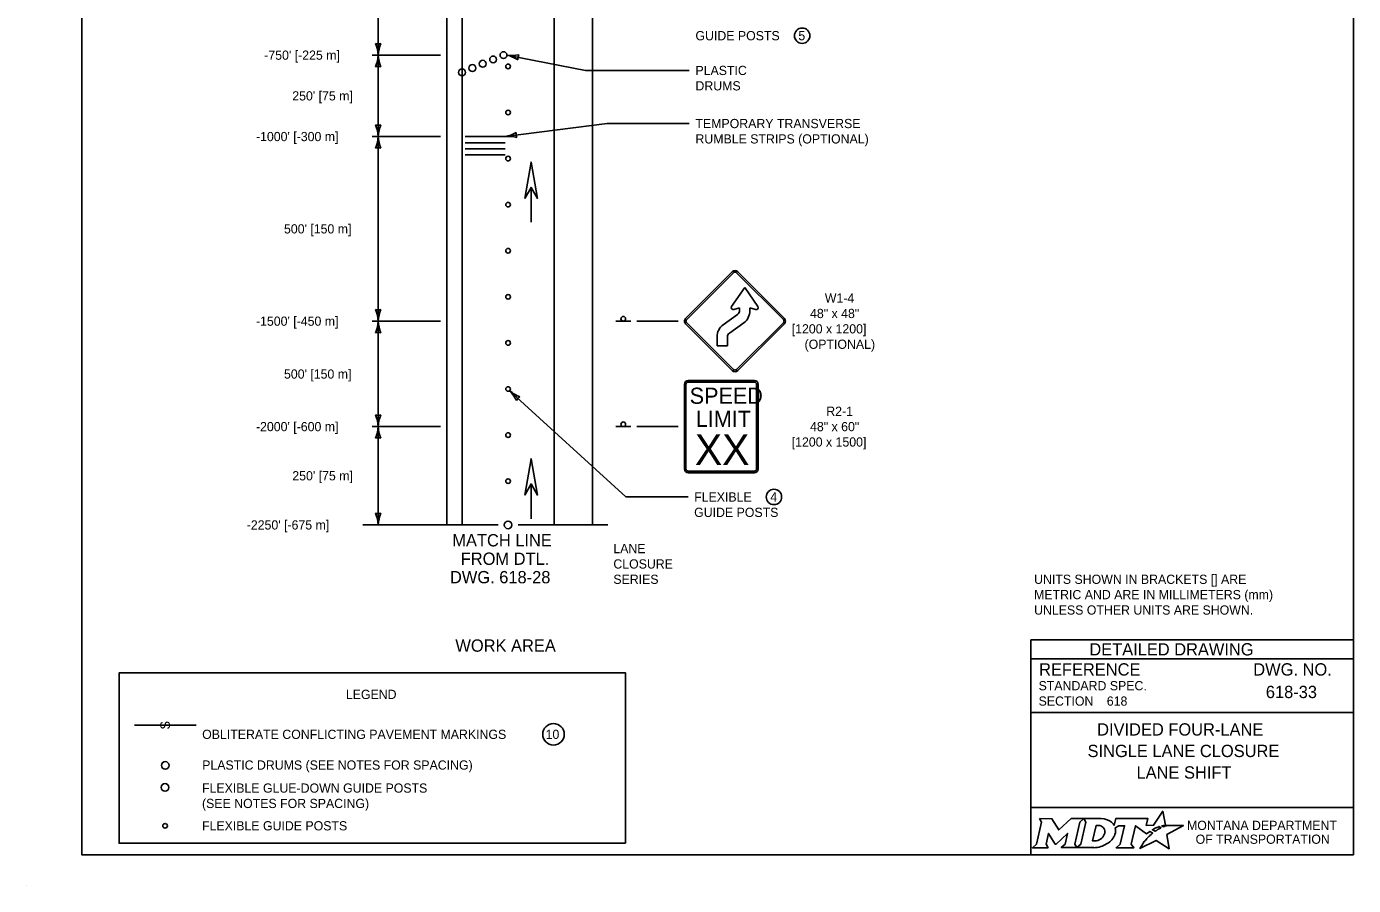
# Model space of a CAD drawing. Extents: x 49991.4 to 50021, y 49987.6 to 50011.4.
# Drawn here: x 49999.98 to 50008.61, y 49999.86 to 50005.45 of the extents above; entities that cross this region are included whole.
import ezdxf

# ---------------------------------------------------------------- set-up
doc = ezdxf.new("R2010")
doc.units = 0
for name, color, linetype in [('Level 1', 7, 'Continuous'), ('Level 2', 7, 'Continuous'), ('Level 3', 7, 'Continuous'), ('Level 6', 7, 'Continuous')]:
    doc.layers.add(name, color=color, linetype=linetype)

msp = doc.modelspace()

# ---------------------------------------------------------------- linework, layer by layer
at = {"layer": 'Level 1'}
for p, q in [((50002.7116, 50002.2097), (50002.7116, 50010.9747)), ((50002.8116, 50002.2097), (50002.8116, 50010.9747)), ((50003.4116, 50002.2102), (50003.4116, 50010.9747)), ((50003.6616, 50002.2101), (50003.6616, 50010.9747)), ((50002.8316, 50004.7381), (50003.0916, 50004.7381)), ((50002.8316, 50004.6981), (50003.0916, 50004.6981)), ((50002.8316, 50004.6581), (50003.0916, 50004.6581)), ((50002.8316, 50004.6181), (50003.0916, 50004.6181)), ((50003.2613, 50004.1817), (50003.2613, 50004.4076)), ((50003.2616, 50004.1817), (50003.2616, 50004.4076)), ((50004.2669, 50003.5539), (50004.571, 50003.8579)), ((50004.274, 50003.5468), (50004.578, 50003.8509)), ((50004.5992, 50003.8509), (50004.9033, 50003.5468)), ((50004.6063, 50003.8579), (50004.9104, 50003.5539)), ((50004.6517, 50003.7546), (50004.5667, 50003.6309)), ((50004.7369, 50003.6309), (50004.6517, 50003.7546)), ((50004.6057, 50003.5805), (50004.5121, 50003.513)), ((50004.5813, 50003.6112), (50004.6178, 50003.623)), ((50004.6178, 50003.623), (50004.6178, 50003.6042)), ((50004.6857, 50003.6042), (50004.6857, 50003.623)), ((50004.6857, 50003.623), (50004.7222, 50003.6112)), ((50003.9096, 50003.5363), (50003.8136, 50003.5363)), ((50004.571, 50003.2145), (50004.2669, 50003.5185)), ((50004.578, 50003.2215), (50004.274, 50003.5256)), ((50004.5518, 50003.4578), (50004.6454, 50003.5254)), ((50004.9033, 50003.5256), (50004.5992, 50003.2215)), ((50004.9104, 50003.5185), (50004.6063, 50003.2145)), ((50004.4718, 50003.4343), (50004.4718, 50003.376)), ((50004.5397, 50003.376), (50004.5397, 50003.4343)), ((50004.4718, 50003.376), (50004.5397, 50003.376)), ((50004.7145, 50003.1497), (50004.2845, 50003.1497)), ((50004.7145, 50003.1397), (50004.2845, 50003.1397)), ((50004.2595, 50003.1247), (50004.2595, 50002.5747)), ((50004.2695, 50003.1247), (50004.2695, 50002.5747)), ((50004.7295, 50002.5747), (50004.7295, 50003.1247)), ((50004.7395, 50002.5747), (50004.7395, 50003.1247)), ((50003.9096, 50002.8497), (50003.8136, 50002.8497)), ((50004.2845, 50002.5597), (50004.7145, 50002.5597)), ((50004.2845, 50002.5497), (50004.7145, 50002.5497)), ((50003.2613, 50002.2504), (50003.2613, 50002.4763)), ((50003.2616, 50002.2504), (50003.2616, 50002.4763)), ((50001.08, 50000.9064), (50000.6789, 50000.9064)), ((49999.9766, 49999.8624), (49999.9766, 49999.8624))]:
    msp.add_line(p, q, dxfattribs=at)
for points in [[(50008.6146, 50011.2628), (50000.3356, 50011.2628), (50000.3356, 50000.0624), (50008.6146, 50000.0624)], [(50003.2196, 50004.3353), (50003.2613, 50004.5718), (50003.3032, 50004.3353), (50003.2613, 50004.4075)], [(50003.2196, 50002.404), (50003.2613, 50002.6405), (50003.3032, 50002.404), (50003.2613, 50002.4762)]]:
    msp.add_lwpolyline(points, close=True, dxfattribs=at)
for centre, radius in [((50002.9466, 50005.2119), 0.0225), ((50003.0141, 50005.24), 0.0225), ((50003.0816, 50005.2681), 0.0225), ((50003.1116, 50005.1947), 0.015), ((50002.8116, 50005.1556), 0.0225), ((50002.8791, 50005.1839), 0.0225), ((50003.1116, 50004.8947), 0.015), ((50003.1116, 50004.5947), 0.015), ((50003.1116, 50004.2947), 0.015), ((50003.1116, 50003.9947), 0.015), ((50003.1116, 50003.6947), 0.015), ((50003.8616, 50003.5515), 0.0152), ((50003.1116, 50003.3947), 0.015), ((50003.1116, 50003.0947), 0.015), ((50003.8616, 50002.8649), 0.0152), ((50003.1116, 50002.7947), 0.015), ((50003.1116, 50002.4947), 0.015), ((50003.1116, 50002.2097), 0.025), ((50000.8793, 50000.6439), 0.025), ((50000.8782, 50000.5009), 0.025), ((50000.8782, 50000.2509), 0.015)]:
    msp.add_circle(centre, radius, dxfattribs=at)
for centre, radius, start, end in [((50004.5886, 50003.8403), 0.025, 45, 135), ((50004.5886, 50003.8403), 0.015, 45, 135), ((50004.5773, 50003.6236), 0.0129, 145.48059, 287.95818), ((50004.5886, 50003.6042), 0.0291, 305.79716, 0), ((50004.5886, 50003.6042), 0.0971, 305.79716, 0), ((50004.7262, 50003.6236), 0.0129, 252.04182, 34.51941), ((50004.2845, 50003.5363), 0.025, 134.99976, 225), ((50004.2845, 50003.5363), 0.015, 134.99976, 225), ((50004.5688, 50003.4343), 0.0971, 125.79716, 180), ((50004.8927, 50003.5363), 0.015, 315, 45), ((50004.8927, 50003.5363), 0.025, 315, 45), ((50004.5688, 50003.4343), 0.0291, 125.79744, 180), ((50004.2845, 50003.1247), 0.025, 90, 180), ((50004.2845, 50003.1247), 0.015, 90, 180), ((50004.5886, 50003.2322), 0.025, 225.00043, 315), ((50004.5886, 50003.2322), 0.015, 225.00043, 315), ((50004.7145, 50003.1247), 0.025, 0, 90), ((50004.7145, 50003.1247), 0.015, 0, 90), ((50004.2845, 50002.5747), 0.025, 180, 270), ((50004.2845, 50002.5747), 0.015, 180, 270), ((50004.7145, 50002.5747), 0.025, 270, 0), ((50004.7145, 50002.5747), 0.015, 270, 0)]:
    msp.add_arc(centre, radius, start, end, dxfattribs=at)
at = {"layer": 'Level 2'}
for p, q in [((50008.6146, 50001.4624), (50006.5146, 50001.4624)), ((50006.5146, 50001.4624), (50006.5146, 50000.0624)), ((50008.6146, 50001.3374), (50006.5146, 50001.3374)), ((50008.2507, 50001.1223), (50008.2507, 50001.1223)), ((50008.6146, 50000.9874), (50006.5146, 50000.9874)), ((50007.0089, 50001.0629), (50007.0089, 50001.0629)), ((50007.5646, 50000.7383), (50007.5646, 50000.7383)), ((50008.6146, 50000.3693), (50006.5146, 50000.3693))]:
    msp.add_line(p, q, dxfattribs=at)
msp.add_lwpolyline([(50003.8763, 50000.1374), (50000.5789, 50000.1374), (50000.5789, 50001.2464), (50003.8763, 50001.2464)], close=True, dxfattribs=at)
for points in [[(50006.5701, 50000.2974), (50006.5842, 50000.274), (50006.5507, 50000.1307), (50006.525, 50000.1082), (50006.6266, 50000.1082), (50006.6131, 50000.131), (50006.6293, 50000.2011), (50006.673, 50000.1321), (50006.6783, 50000.1321), (50006.7534, 50000.2016), (50006.737, 50000.1305), (50006.7123, 50000.1085), (50006.8139, 50000.1085), (50006.8001, 50000.1318), (50006.8333, 50000.2742)], [(50006.8333, 50000.2742), (50006.8586, 50000.2974), (50006.7762, 50000.2974), (50006.6966, 50000.2244), (50006.6521, 50000.2971), (50006.5701, 50000.2974)], [(50006.9722, 50000.2974), (50006.8586, 50000.2974), (50006.8733, 50000.2745), (50006.8394, 50000.1307), (50006.8139, 50000.1085), (50006.9245, 50000.1085)], [(50007.3771, 50000.2447), (50007.3668, 50000.2503), (50007.3784, 50000.2531), (50007.39, 50000.2551), (50007.3726, 50000.3452), (50007.3131, 50000.2539), (50007.2658, 50000.2532), (50007.2761, 50000.2973), (50007.0669, 50000.2974), (50007.0568, 50000.2549), (50007.051, 50000.2632)], [(50006.9962, 50000.2107), (50006.995, 50000.2026), (50006.9918, 50000.1933), (50006.9876, 50000.1851), (50006.982, 50000.1776), (50006.9755, 50000.1707), (50006.9676, 50000.1644), (50006.9593, 50000.1597), (50006.9502, 50000.1558), (50006.9411, 50000.1535), (50006.9319, 50000.1526), (50006.916, 50000.1526), (50006.9396, 50000.2526), (50006.9556, 50000.2526), (50006.9632, 50000.252), (50006.9708, 50000.2501), (50006.9774, 50000.2471), (50006.9835, 50000.2429), (50006.9883, 50000.2379), (50006.992, 50000.2319), (50006.9947, 50000.2257), (50006.9963, 50000.2183), (50006.9963, 50000.2153), (50006.9962, 50000.2107)], [(50007.0636, 50000.2383), (50007.0882, 50000.2514), (50007.1251, 50000.2514), (50007.0965, 50000.1309), (50007.069, 50000.1082), (50007.1852, 50000.1082), (50007.1682, 50000.1311), (50007.1964, 50000.2513), (50007.2677, 50000.1996), (50007.2888, 50000.2147), (50007.3085, 50000.2038)], [(50007.2527, 50000.1479), (50007.2374, 50000.1235), (50007.2327, 50000.116), (50007.2269, 50000.1074), (50007.2246, 50000.1031), (50007.3299, 50000.1562), (50007.4138, 50000.1011), (50007.4007, 50000.1938), (50007.5076, 50000.2522), (50007.4583, 50000.253), (50007.4282, 50000.2534), (50007.4074, 50000.2537), (50007.4006, 50000.2522), (50007.3957, 50000.251), (50007.3873, 50000.2487), (50007.3771, 50000.2447)], [(50007.3267, 50000.2171), (50007.3243, 50000.2154), (50007.306, 50000.225), (50007.3163, 50000.2307), (50007.3204, 50000.2329), (50007.329, 50000.2369), (50007.3347, 50000.2395), (50007.3426, 50000.2425), (50007.3499, 50000.2452), (50007.3617, 50000.2378), (50007.3577, 50000.2357), (50007.3531, 50000.2332), (50007.3489, 50000.231), (50007.3439, 50000.2281), (50007.342, 50000.227), (50007.3393, 50000.2254), (50007.3368, 50000.224), (50007.3345, 50000.2224), (50007.3319, 50000.2206), (50007.3292, 50000.2188), (50007.3267, 50000.2171)], [(50006.9702, 50000.1158), (50006.9786, 50000.1184), (50006.9916, 50000.1238), (50007.012, 50000.1348)], [(50007.2666, 50000.164), (50007.2666, 50000.164)]]:
    msp.add_lwpolyline(points, dxfattribs=at)
for centre, radius in [((50005.0257, 50005.3948), 0.05), ((50004.8422, 50002.3916), 0.05), ((50003.407, 50000.8464), 0.07)]:
    msp.add_circle(centre, radius, dxfattribs=at)
for centre, radius, start, end in [((50006.9953, 50000.219), 0.0709, 339.53292, 15.85821), ((50006.9513, 50000.2363), 0.1183, 300.91025, 339.13831)]:
    msp.add_arc(centre, radius, start, end, dxfattribs=at)
for centre, major_axis, ratio, start_param, end_param in [((50006.9701, 50000.25), (0.0834, -0.0037), 0.568097, 0.61298, 1.570796), ((50007.0257, 50000.2573), (0.0361, -0.0295), 0.469099, 1.225588, 1.570796), ((50007.2974, 50000.1941), (-0.0112, -0.0097), 0.021651, 3.157348, 6.283185), ((50006.9248, 50000.2568), (0, 0.1484), 0.987302, 3.139398, 3.456847), ((50007.2597, 50000.1559), (-0.00694, -0.00806), 0.008222, 0, 3.137361), ((50007.2764, 50000.1742), (-0.0098, -0.0102), 0.016458, 3.141593, 6.279097)]:
    msp.add_ellipse(centre, major_axis=major_axis, ratio=ratio, start_param=start_param, end_param=end_param, dxfattribs=at)
at = {"layer": 'Level 3'}
for p, q in [((50002.2659, 50005.7947), (50002.2659, 50005.2681)), ((50002.2259, 50005.2681), (50002.6716, 50005.2681)), ((50002.2659, 50005.2681), (50002.2659, 50004.7381)), ((50003.1041, 50005.2681), (50003.6163, 50005.1685)), ((50003.6163, 50005.1685), (50004.2911, 50005.1685)), ((50003.0916, 50004.7381), (50003.7572, 50004.823)), ((50003.7572, 50004.823), (50004.2911, 50004.823)), ((50002.2259, 50004.7381), (50002.6716, 50004.7381)), ((50002.2659, 50004.7381), (50002.2659, 50004.2081)), ((50002.2659, 50004.2081), (50002.2659, 50003.5363)), ((50002.2259, 50003.5363), (50002.6716, 50003.5363)), ((50002.266, 50002.8478), (50002.266, 50003.5363)), ((50003.9496, 50003.5363), (50004.2195, 50003.5363)), ((50003.1216, 50003.0835), (50003.8787, 50002.3917)), ((50002.2259, 50002.8497), (50002.6716, 50002.8497)), ((50002.2659, 50002.2097), (50002.2659, 50002.8497)), ((50003.9496, 50002.8497), (50004.2195, 50002.8497)), ((50003.8787, 50002.3917), (50004.2827, 50002.3917))]:
    msp.add_line(p, q, dxfattribs=at)
for centre, radius, start, end in [((50002.0438, 50005.259), 0.2223, 2.36048, 22.54399), ((50002.2659, 50005.3963), 0.0548, 252.13882, 287.86118), ((50002.4986, 50005.2566), 0.233, 157.92284, 177.17269), ((50002.0438, 50005.2773), 0.2223, 337.45601, 357.63952), ((50002.4986, 50005.2796), 0.233, 182.82731, 202.07716), ((50003.1372, 50005.4987), 0.233, 261.82875, 281.0786), ((50003.0527, 50005.0518), 0.2223, 56.45745, 76.64095), ((50003.2299, 50005.2436), 0.0548, 151.14025, 186.86262), ((50002.2659, 50005.1399), 0.0548, 72.13882, 107.86118), ((50002.0438, 50004.729), 0.2223, 2.36048, 22.54399), ((50002.2659, 50004.8663), 0.0548, 252.13882, 287.86118), ((50002.4986, 50004.7266), 0.233, 157.92284, 177.17269), ((50002.0438, 50004.7473), 0.2223, 337.45601, 357.63952), ((50002.4986, 50004.7496), 0.233, 182.82731, 202.07716), ((50003.0507, 50004.9675), 0.233, 280.09235, 299.3422), ((50003.1106, 50004.5166), 0.2223, 74.72105, 94.90455), ((50003.2188, 50004.7543), 0.0548, 169.40385, 205.12621), ((50002.2659, 50004.6099), 0.0548, 72.13882, 107.86118), ((50002.0438, 50003.5271), 0.2223, 2.36048, 22.54399), ((50002.2659, 50003.6645), 0.0548, 252.13882, 287.86118), ((50002.4986, 50003.5248), 0.233, 157.92284, 177.17269), ((50002.0438, 50003.5454), 0.2223, 337.45601, 357.63952), ((50002.4986, 50003.5478), 0.233, 182.82731, 202.07716), ((50002.2659, 50003.4081), 0.0548, 72.13882, 107.86118), ((50003.2678, 50003.251), 0.2223, 228.88386, 249.06736), ((50002.9531, 50002.9226), 0.233, 24.44621, 43.69606), ((50003.2146, 50002.9953), 0.0548, 118.66219, 154.38456), ((50002.2659, 50002.9779), 0.0548, 252.13882, 287.86118), ((50002.0332, 50002.8382), 0.233, 2.82731, 22.07716), ((50002.488, 50002.8405), 0.2223, 157.45601, 177.63952), ((50002.0332, 50002.8612), 0.233, 337.92284, 357.17269), ((50002.488, 50002.8588), 0.2223, 182.36048, 202.54399), ((50002.2659, 50002.7215), 0.0548, 72.13882, 107.86118), ((50002.0438, 50002.2005), 0.2223, 2.36048, 22.54399), ((50002.2659, 50002.3379), 0.0548, 252.13882, 287.86118), ((50002.4986, 50002.1982), 0.233, 157.92284, 177.17269)]:
    msp.add_arc(centre, radius, start, end, dxfattribs=at)
at = {"layer": 'Level 6'}
for p, q in [((50002.1659, 50002.2097), (50003.0466, 50002.2097)), ((50003.1766, 50002.2104), (50003.7616, 50002.21))]:
    msp.add_line(p, q, dxfattribs=at)

# ---------------------------------------------------------------- texts
at = {"layer": 'Level 1'}
for s, height, p in [('SPEED', 0.10512, (50004.2935, 50002.9981)), ('LIMIT', 0.10512, (50004.3333, 50002.848)), ('XX', 0.19892, (50004.3275, 50002.6007))]:
    msp.add_text(s, height=height, dxfattribs=at).set_placement(p)
msp.add_text('S', height=0.0625, rotation=90, dxfattribs=at).set_placement((50000.9101, 50000.8774))
at = {"layer": 'Level 2'}
for s, height, p in [('GUIDE POSTS', 0.06, (50004.3311, 50005.3648)), ('5', 0.06, (50005.0009, 50005.3651)), ("-750' [-225 m]", 0.06, (50001.524, 50005.2381)), ('PLASTIC', 0.06, (50004.3311, 50005.1385)), ('DRUMS', 0.06, (50004.3311, 50005.0385)), ("250' [75 m]", 0.06, (50001.7064, 50004.9731)), ('TEMPORARY TRANSVERSE', 0.06, (50004.3311, 50004.7929)), ("-1000' [-300 m]", 0.06, (50001.4701, 50004.7081)), ('RUMBLE STRIPS (OPTIONAL)', 0.06, (50004.3311, 50004.6929)), ("500' [150 m]", 0.06, (50001.6525, 50004.1072)), (' W1-4 ', 0.06, (50005.1511, 50003.6566)), ("-1500' [-450 m]", 0.06, (50001.4701, 50003.5063)), ('48" x 48"', 0.06, (50005.0771, 50003.5564)), ('[1200 x 1200]', 0.06, (50004.9577, 50003.4562)), ('(OPTIONAL)', 0.06, (50005.0414, 50003.356)), ("500' [150 m]", 0.06, (50001.6525, 50003.1621)), ('R2-1', 0.06, (50005.1827, 50002.9197)), ("-2000' [-600 m]", 0.06, (50001.4701, 50002.8197)), ('48" x 60"', 0.06, (50005.0771, 50002.8197)), ('[1200 x 1500]', 0.06, (50004.9577, 50002.7197)), ("250' [75 m]", 0.06, (50001.7067, 50002.4997)), ('FLEXIBLE', 0.06, (50004.3227, 50002.3616)), ('4', 0.06, (50004.8182, 50002.3616)), ('GUIDE POSTS', 0.06, (50004.3227, 50002.2616)), ("-2250' [-675 m]", 0.06, (50001.4101, 50002.1797)), ('MATCH LINE', 0.08, (50002.7482, 50002.0697)), ('FROM DTL.', 0.08, (50002.8032, 50001.9497)), ('LANE', 0.06, (50003.7966, 50002.0257)), ('CLOSURE', 0.06, (50003.7966, 50001.9257)), ('DWG. 618-28', 0.08, (50002.733, 50001.8297)), ('SERIES', 0.06, (50003.7966, 50001.8257)), ('UNITS SHOWN IN BRACKETS [] ARE ', 0.06, (50006.5355, 50001.8259)), ('METRIC AND ARE IN MILLIMETERS (mm) ', 0.06, (50006.5355, 50001.7259)), ('UNLESS OTHER UNITS ARE SHOWN.', 0.06, (50006.5355, 50001.6259)), ('WORK AREA', 0.08, (50002.7682, 50001.3843)), ('DETAILED DRAWING', 0.0799, (50006.8956, 50001.3599)), ('REFERENCE', 0.08, (50006.5682, 50001.229)), ('DWG. NO.', 0.08, (50007.9624, 50001.229)), ('STANDARD SPEC.', 0.06, (50006.5649, 50001.133)), ('618-33', 0.08, (50008.0441, 50001.0823)), ('LEGEND', 0.06, (50002.0552, 50001.0764)), ('SECTION', 0.06, (50006.5649, 50001.033)), ('618', 0.06, (50007.0089, 50001.0329)), ('DIVIDED FOUR-LANE', 0.08, (50006.946, 50000.8383)), ('OBLITERATE CONFLICTING PAVEMENT MARKINGS', 0.06, (50001.12, 50000.8164)), ('10', 0.06, (50003.3557, 50000.8164)), ('SINGLE LANE CLOSURE', 0.08, (50006.8837, 50000.6983)), ('PLASTIC DRUMS (SEE NOTES FOR SPACING)', 0.06, (50001.12, 50000.6164)), ('LANE SHIFT', 0.08, (50007.2023, 50000.5583)), ('FLEXIBLE GLUE-DOWN GUIDE POSTS', 0.06, (50001.1189, 50000.4664)), ('(SEE NOTES FOR SPACING)', 0.06, (50001.1189, 50000.3664)), ('FLEXIBLE GUIDE POSTS', 0.06, (50001.1189, 50000.2209)), ('MONTANA DEPARTMENT', 0.06, (50007.5308, 50000.2236)), ('OF TRANSPORTATION', 0.06, (50007.587, 50000.1336))]:
    msp.add_text(s, height=height, dxfattribs=at).set_placement(p)

doc.saveas('drawing.dxf')
